(* Logix 5000 project; controller Test vendor 1 type 14 code 92 rev 33.11; software revision 33.03; part 2 of 3 *)
(* tags used below, declared in another part *)
   K50 : Banner_K50Display_v4;
   Port_Data : Banner_IOL_Port_v4;
   Port : DINT;
   Local_Control : DINT;
   Command_Being_Processed : BOOL;
   Update_Archive : BOOL;
   Index_Write_Control : DINT;
   Index_Write_Inprocess : INT;
   Inprocess_Index : DINT;
   SP_Index : DINT;   // State Parameters Index
   SP_Write_Index : DINT;
   SP_W_Index : DINT;
(* Banner_K50Display_Param_v4, continued *)

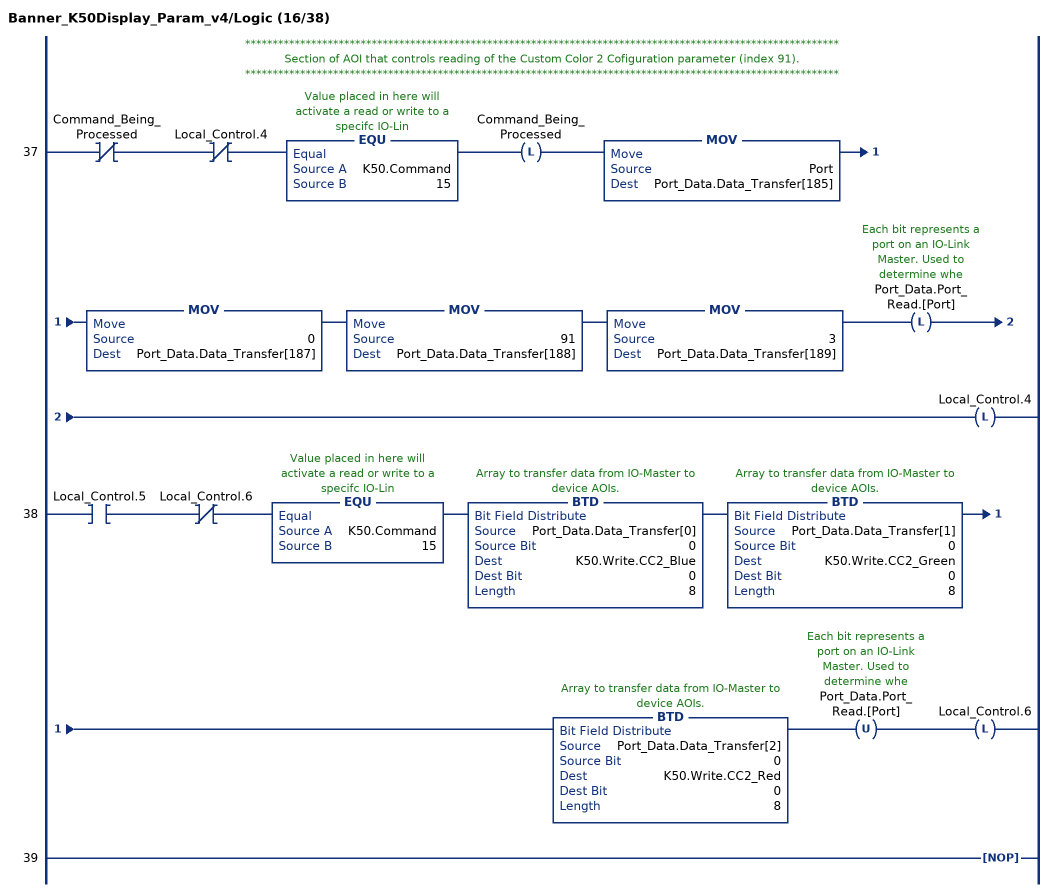
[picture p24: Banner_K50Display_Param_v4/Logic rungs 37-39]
   // ************************************************************************************************************
   // Section of AOI that controls reading of the Custom Color 2 Cofiguration parameter (index 91).
   // ************************************************************************************************************
   37: XIO(Command_Being_Processed)XIO(Local_Control.4)EQU(K50.Command,15)OTL(Command_Being_Processed)MOV(Port,Port_Data.Data_Transfer[185])MOV(0,Port_Data.Data_Transfer[187])MOV(91,Port_Data.Data_Transfer[188])MOV(3,Port_Data.Data_Transfer[189])OTL(Port_Data.Port_Read.[Port])OTL(Local_Control.4);
   38: XIC(Local_Control.5)XIO(Local_Control.6)EQU(K50.Command,15)BTD(Port_Data.Data_Transfer[0],0,K50.Write.CC2_Blue,0,8)BTD(Port_Data.Data_Transfer[1],0,K50.Write.CC2_Green,0,8)BTD(Port_Data.Data_Transfer[2],0,K50.Write.CC2_Red,0,8)OTU(Port_Data.Port_Read.[Port])OTL(Local_Control.6);
   39: NOP();
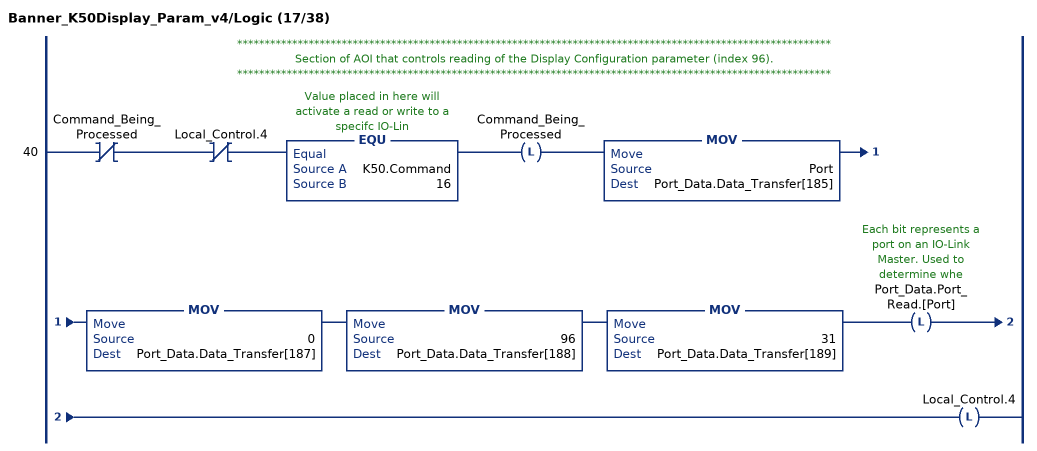
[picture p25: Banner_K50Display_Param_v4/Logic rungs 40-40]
   // ************************************************************************************************************
   // Section of AOI that controls reading of the Display Configuration parameter (index 96).
   // ************************************************************************************************************
   40: XIO(Command_Being_Processed)XIO(Local_Control.4)EQU(K50.Command,16)OTL(Command_Being_Processed)MOV(Port,Port_Data.Data_Transfer[185])MOV(0,Port_Data.Data_Transfer[187])MOV(96,Port_Data.Data_Transfer[188])MOV(31,Port_Data.Data_Transfer[189])OTL(Port_Data.Port_Read.[Port])OTL(Local_Control.4);
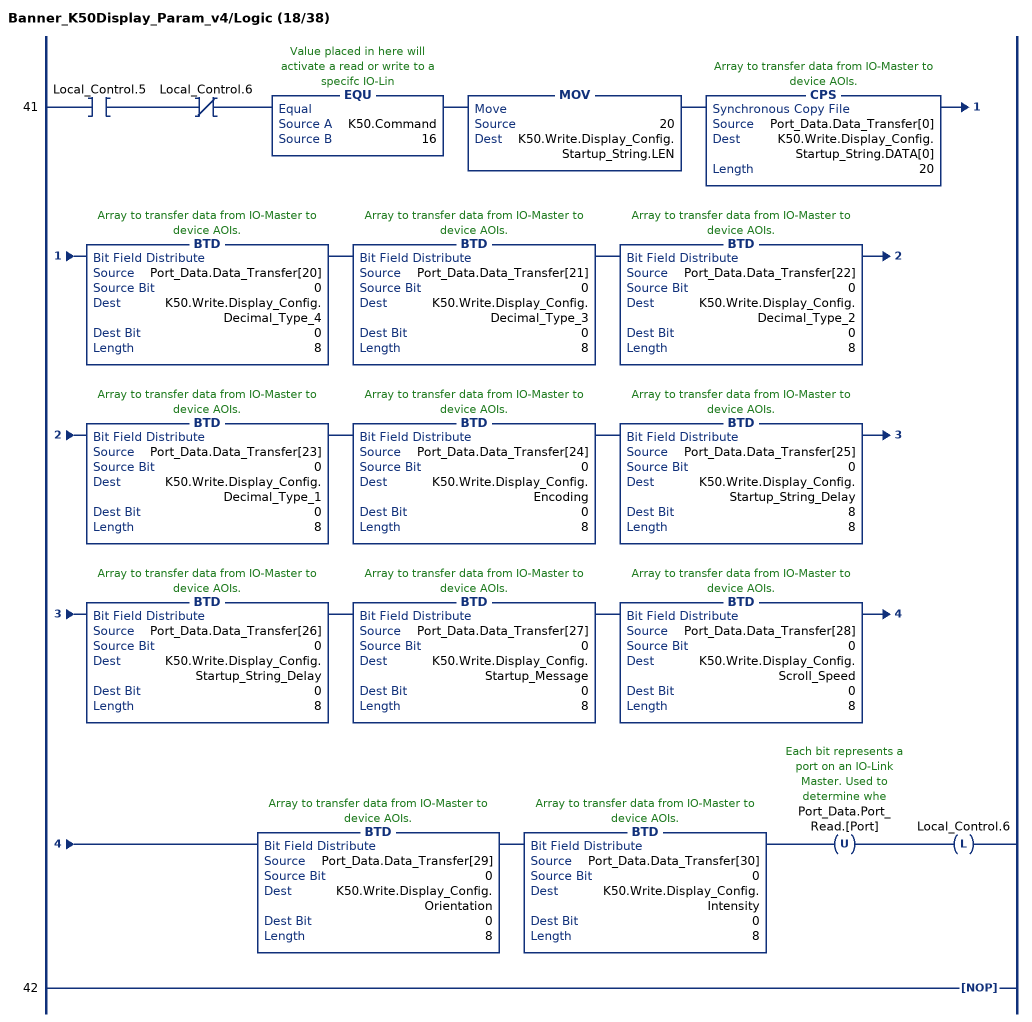
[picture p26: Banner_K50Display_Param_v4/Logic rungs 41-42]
   41: XIC(Local_Control.5)XIO(Local_Control.6)EQU(K50.Command,16)MOV(20,K50.Write.Display_Config.Startup_String.LEN)CPS(Port_Data.Data_Transfer[0],K50.Write.Display_Config.Startup_String.DATA[0],20)BTD(Port_Data.Data_Transfer[20],0,K50.Write.Display_Config.Decimal_Type_4,0,8)BTD(Port_Data.Data_Transfer[21],0,K50.Write.Display_Config.Decimal_Type_3,0,8)BTD(Port_Data.Data_Transfer[22],0,K50.Write.Display_Config.Decimal_Type_2,0,8)BTD(Port_Data.Data_Transfer[23],0,K50.Write.Display_Config.Decimal_Type_1,0,8)BTD(Port_Data.Data_Transfer[24],0,K50.Write.Display_Config.Encoding,0,8)BTD(Port_Data.Data_Transfer[25],0,K50.Write.Display_Config.Startup_String_Delay,8,8)BTD(Port_Data.Data_Transfer[26],0,K50.Write.Display_Config.Startup_String_Delay,0,8)BTD(Port_Data.Data_Transfer[27],0,K50.Write.Display_Config.Startup_Message,0,8)BTD(Port_Data.Data_Transfer[28],0,K50.Write.Display_Config.Scroll_Speed,0,8)BTD(Port_Data.Data_Transfer[29],0,K50.Write.Display_Config.Orientation,0,8)BTD(Port_Data.Data_Transfer[30],0,K50.Write.Display_Config.Intensity,0,8)OTU(Port_Data.Port_Read.[Port])OTL(Local_Control.6);
   42: NOP();
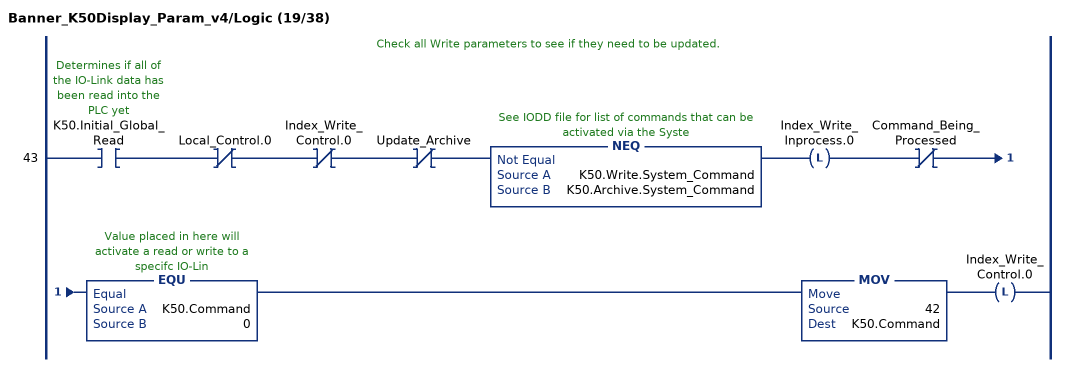
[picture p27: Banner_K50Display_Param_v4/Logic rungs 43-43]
   // Check all Write parameters to see if they need to be updated.
   43: XIC(K50.Initial_Global_Read)XIO(Local_Control.0)XIO(Index_Write_Control.0)XIO(Update_Archive)NEQ(K50.Write.System_Command,K50.Archive.System_Command)OTL(Index_Write_Inprocess.0)XIO(Command_Being_Processed)EQU(K50.Command,0)MOV(42,K50.Command)OTL(Index_Write_Control.0);
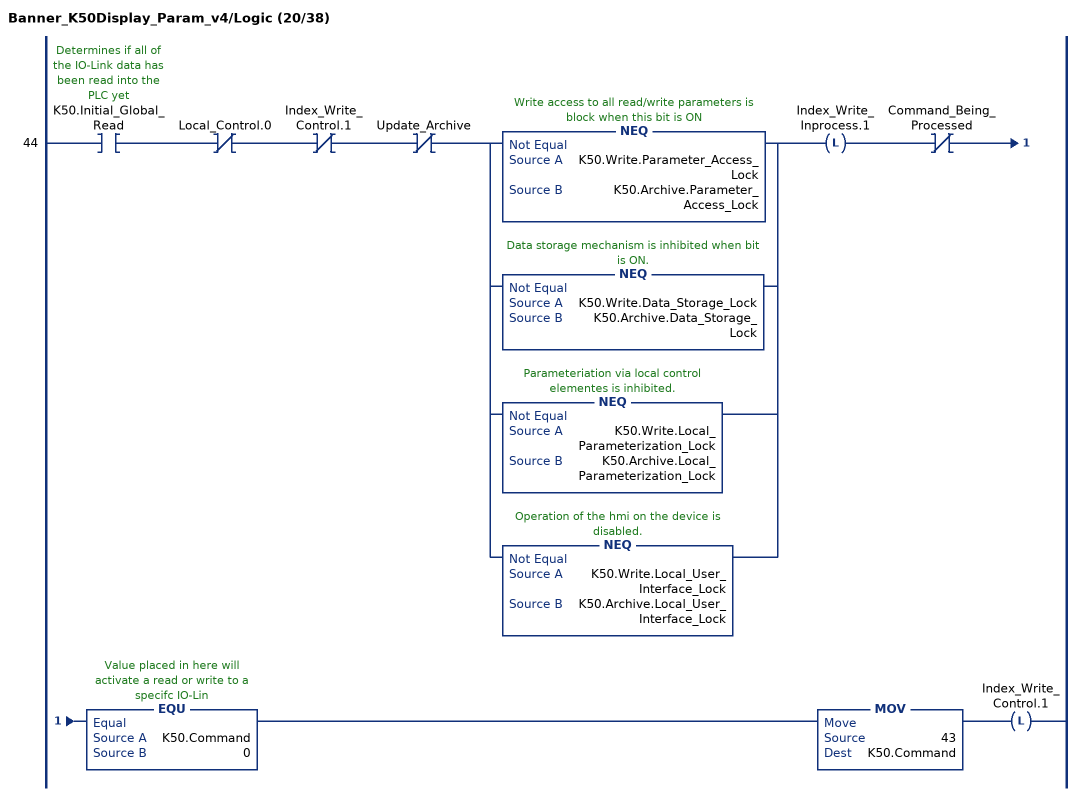
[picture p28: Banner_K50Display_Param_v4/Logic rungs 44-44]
   44: XIC(K50.Initial_Global_Read)XIO(Local_Control.0)XIO(Index_Write_Control.1)XIO(Update_Archive)[NEQ(K50.Write.Parameter_Access_Lock,K50.Archive.Parameter_Access_Lock) ,NEQ(K50.Write.Data_Storage_Lock,K50.Archive.Data_Storage_Lock) ,NEQ(K50.Write.Local_Parameterization_Lock,K50.Archive.Local_Parameterization_Lock) ,NEQ(K50.Write.Local_User_Interface_Lock,K50.Archive.Local_User_Interface_Lock) ]OTL(Index_Write_Inprocess.1)XIO(Command_Being_Processed)EQU(K50.Command,0)MOV(43,K50.Command)OTL(Index_Write_Control.1);
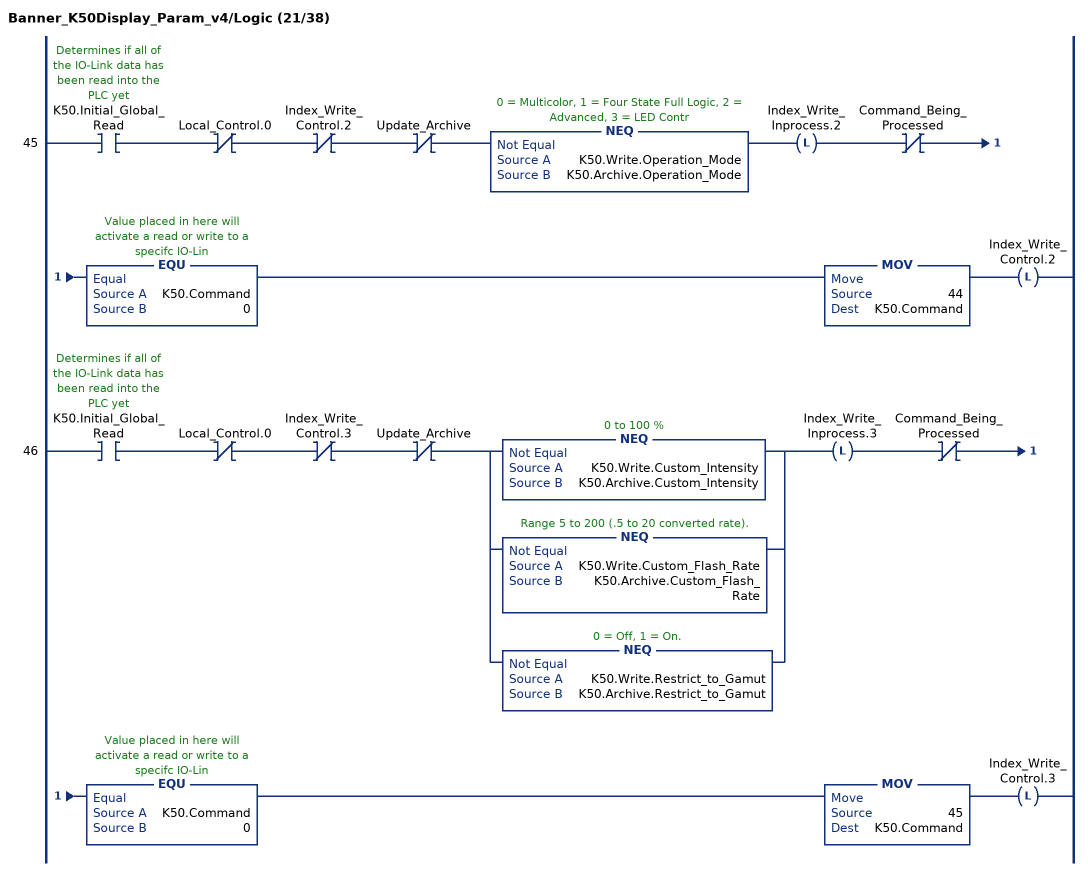
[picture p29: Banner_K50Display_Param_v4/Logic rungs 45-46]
   45: XIC(K50.Initial_Global_Read)XIO(Local_Control.0)XIO(Index_Write_Control.2)XIO(Update_Archive)NEQ(K50.Write.Operation_Mode,K50.Archive.Operation_Mode)OTL(Index_Write_Inprocess.2)XIO(Command_Being_Processed)EQU(K50.Command,0)MOV(44,K50.Command)OTL(Index_Write_Control.2);
   46: XIC(K50.Initial_Global_Read)XIO(Local_Control.0)XIO(Index_Write_Control.3)XIO(Update_Archive)[NEQ(K50.Write.Custom_Intensity,K50.Archive.Custom_Intensity) ,NEQ(K50.Write.Custom_Flash_Rate,K50.Archive.Custom_Flash_Rate) ,NEQ(K50.Write.Restrict_to_Gamut,K50.Archive.Restrict_to_Gamut) ]OTL(Index_Write_Inprocess.3)XIO(Command_Being_Processed)EQU(K50.Command,0)MOV(45,K50.Command)OTL(Index_Write_Control.3);
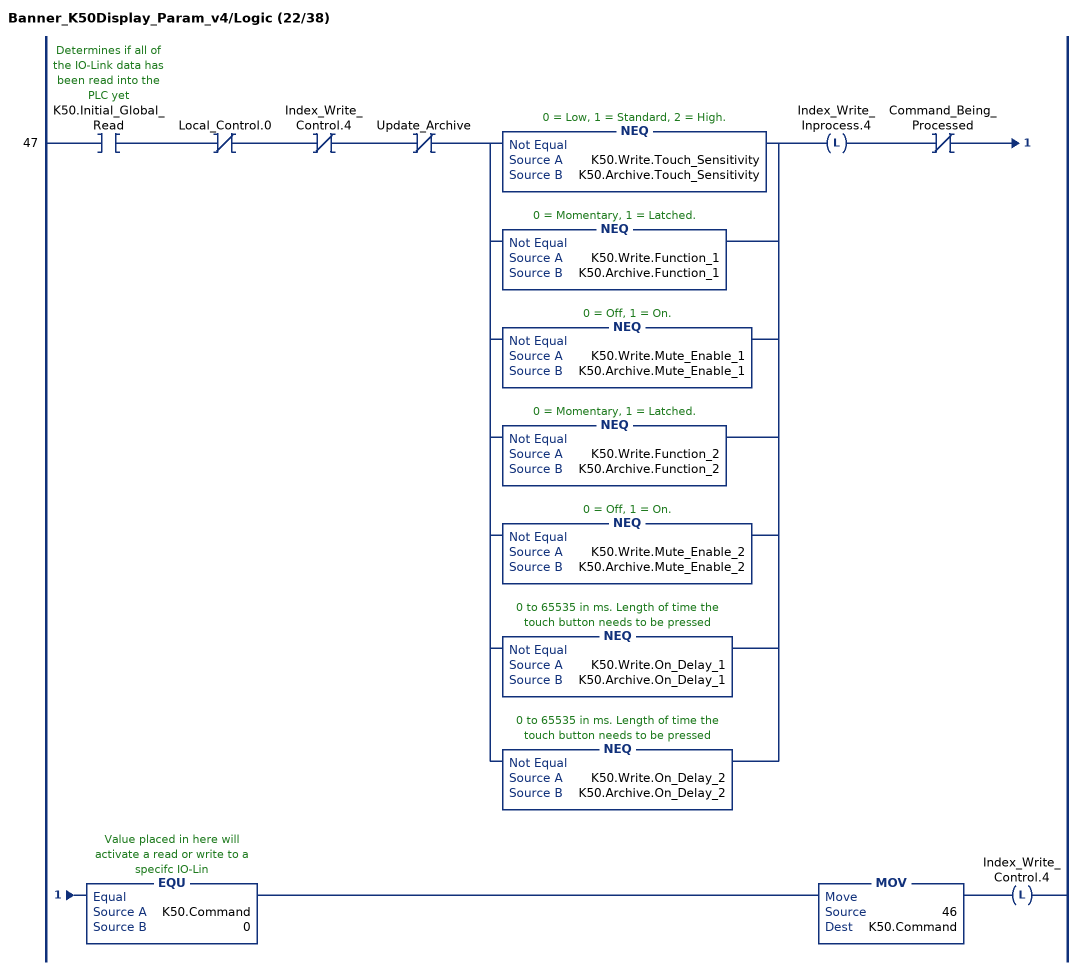
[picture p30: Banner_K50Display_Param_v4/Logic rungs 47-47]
   47: XIC(K50.Initial_Global_Read)XIO(Local_Control.0)XIO(Index_Write_Control.4)XIO(Update_Archive)[NEQ(K50.Write.Touch_Sensitivity,K50.Archive.Touch_Sensitivity) ,NEQ(K50.Write.Function_1,K50.Archive.Function_1) ,NEQ(K50.Write.Mute_Enable_1,K50.Archive.Mute_Enable_1) ,NEQ(K50.Write.Function_2,K50.Archive.Function_2) ,NEQ(K50.Write.Mute_Enable_2,K50.Archive.Mute_Enable_2) ,NEQ(K50.Write.On_Delay_1,K50.Archive.On_Delay_1) ,NEQ(K50.Write.On_Delay_2,K50.Archive.On_Delay_2) ]OTL(Index_Write_Inprocess.4)XIO(Command_Being_Processed)EQU(K50.Command,0)MOV(46,K50.Command)OTL(Index_Write_Control.4);
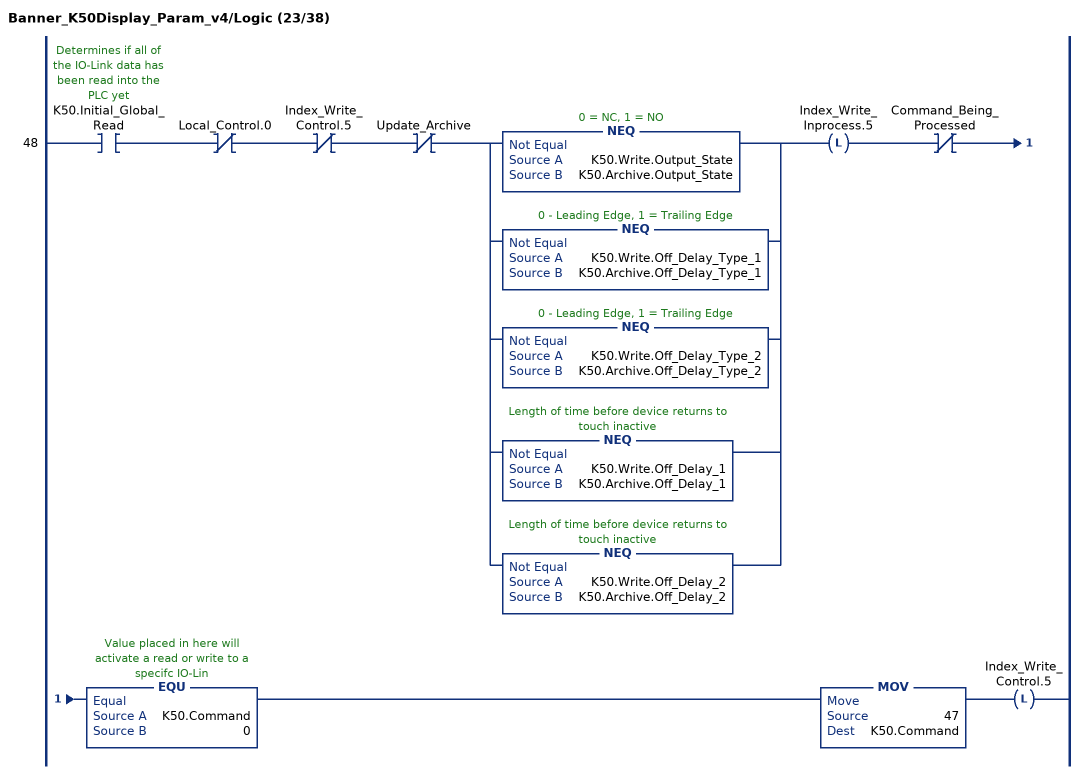
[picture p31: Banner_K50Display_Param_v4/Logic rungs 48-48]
   48: XIC(K50.Initial_Global_Read)XIO(Local_Control.0)XIO(Index_Write_Control.5)XIO(Update_Archive)[NEQ(K50.Write.Output_State,K50.Archive.Output_State) ,NEQ(K50.Write.Off_Delay_Type_1,K50.Archive.Off_Delay_Type_1) ,NEQ(K50.Write.Off_Delay_Type_2,K50.Archive.Off_Delay_Type_2) ,NEQ(K50.Write.Off_Delay_1,K50.Archive.Off_Delay_1) ,NEQ(K50.Write.Off_Delay_2,K50.Archive.Off_Delay_2) ]OTL(Index_Write_Inprocess.5)XIO(Command_Being_Processed)EQU(K50.Command,0)MOV(47,K50.Command)OTL(Index_Write_Control.5);
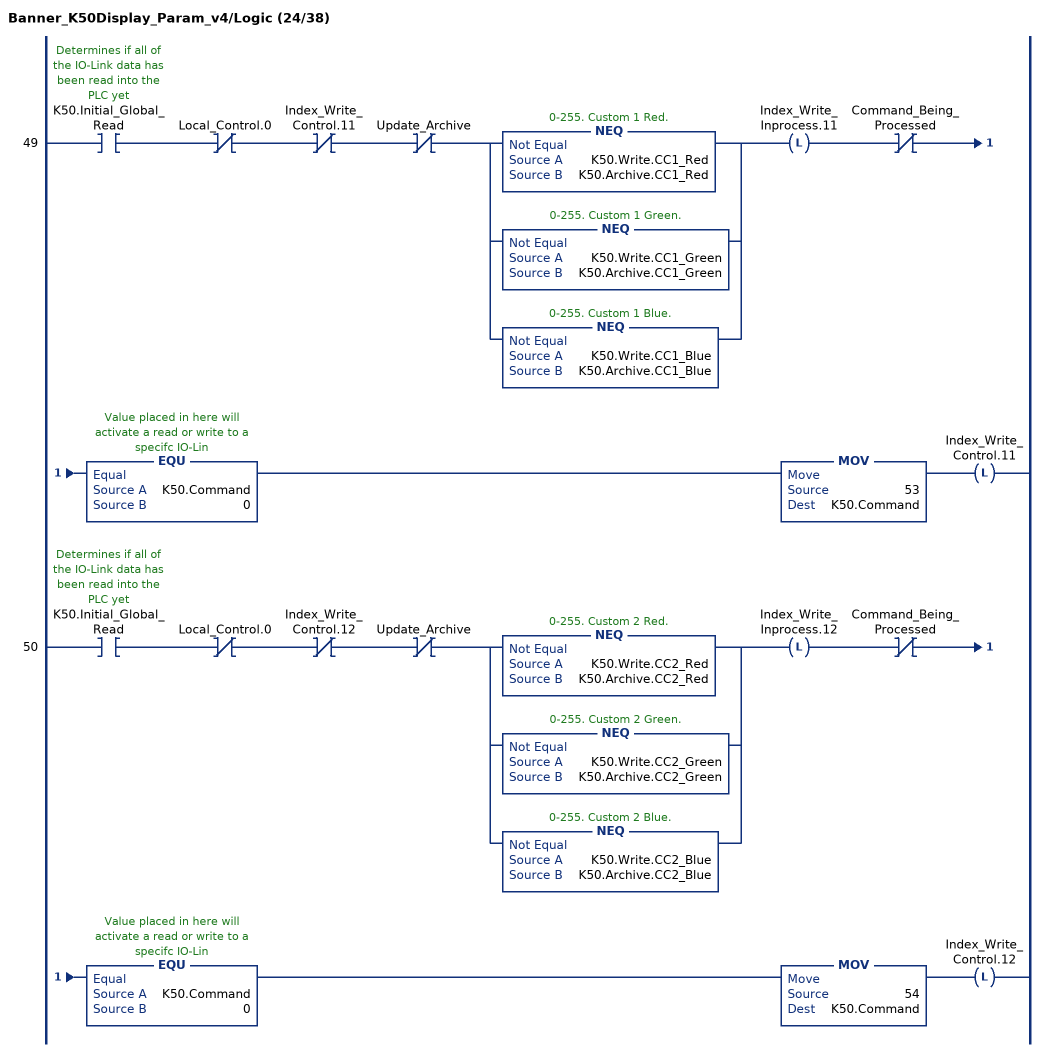
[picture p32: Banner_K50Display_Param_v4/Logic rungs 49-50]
   49: XIC(K50.Initial_Global_Read)XIO(Local_Control.0)XIO(Index_Write_Control.11)XIO(Update_Archive)[NEQ(K50.Write.CC1_Red,K50.Archive.CC1_Red) ,NEQ(K50.Write.CC1_Green,K50.Archive.CC1_Green) ,NEQ(K50.Write.CC1_Blue,K50.Archive.CC1_Blue) ]OTL(Index_Write_Inprocess.11)XIO(Command_Being_Processed)EQU(K50.Command,0)MOV(53,K50.Command)OTL(Index_Write_Control.11);
   50: XIC(K50.Initial_Global_Read)XIO(Local_Control.0)XIO(Index_Write_Control.12)XIO(Update_Archive)[NEQ(K50.Write.CC2_Red,K50.Archive.CC2_Red) ,NEQ(K50.Write.CC2_Green,K50.Archive.CC2_Green) ,NEQ(K50.Write.CC2_Blue,K50.Archive.CC2_Blue) ]OTL(Index_Write_Inprocess.12)XIO(Command_Being_Processed)EQU(K50.Command,0)MOV(54,K50.Command)OTL(Index_Write_Control.12);
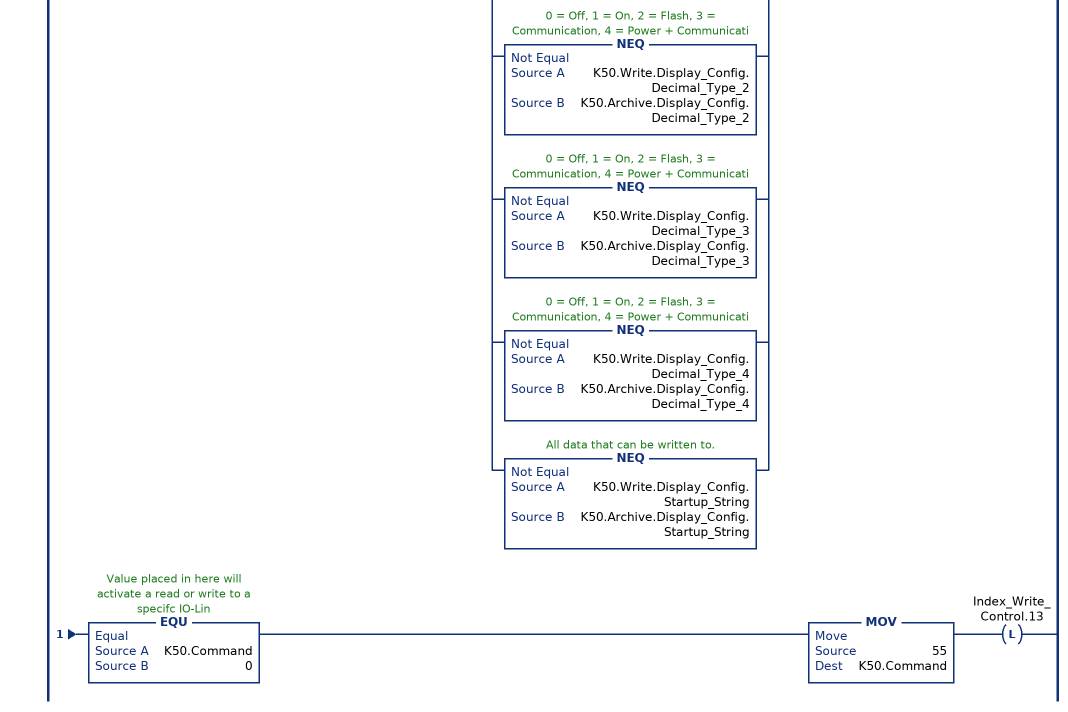
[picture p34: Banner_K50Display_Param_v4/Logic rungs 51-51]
   51: XIC(K50.Initial_Global_Read)XIO(Local_Control.0)XIO(Index_Write_Control.13)XIO(Update_Archive)[NEQ(K50.Write.Display_Config.Intensity,K50.Archive.Display_Config.Intensity) ,NEQ(K50.Write.Display_Config.Orientation,K50.Archive.Display_Config.Orientation) ,NEQ(K50.Write.Display_Config.Scroll_Speed,K50.Archive.Display_Config.Scroll_Speed) ,NEQ(K50.Write.Display_Config.Startup_Message,K50.Archive.Display_Config.Startup_Message) ,NEQ(K50.Write.Display_Config.Startup_String_Delay,K50.Archive.Display_Config.Startup_String_Delay) ,NEQ(K50.Write.Display_Config.Encoding,K50.Archive.Display_Config.Encoding) ,NEQ(K50.Write.Display_Config.Decimal_Type_1,K50.Archive.Display_Config.Decimal_Type_1) ,NEQ(K50.Write.Display_Config.Decimal_Type_2,K50.Archive.Display_Config.Decimal_Type_2) ,NEQ(K50.Write.Display_Config.Decimal_Type_3,K50.Archive.Display_Config.Decimal_Type_3) ,NEQ(K50.Write.Display_Config.Decimal_Type_4,K50.Archive.Display_Config.Decimal_Type_4) ,NEQ(K50.Write.Display_Config.Startup_String,K50.Archive.Display_Config.Startup_String) ]OTL(Index_Write_Inprocess.13)XIO(Command_Being_Processed)EQU(K50.Command,0)MOV(55,K50.Command)OTL(Index_Write_Control.13);
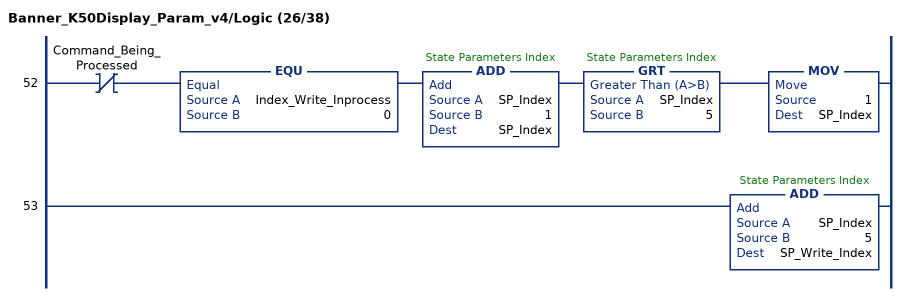
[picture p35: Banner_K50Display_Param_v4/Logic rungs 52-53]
   52: XIO(Command_Being_Processed)EQU(Index_Write_Inprocess,0)ADD(SP_Index,1,SP_Index)GRT(SP_Index,5)MOV(1,SP_Index);
   53: ADD(SP_Index,5,SP_Write_Index);
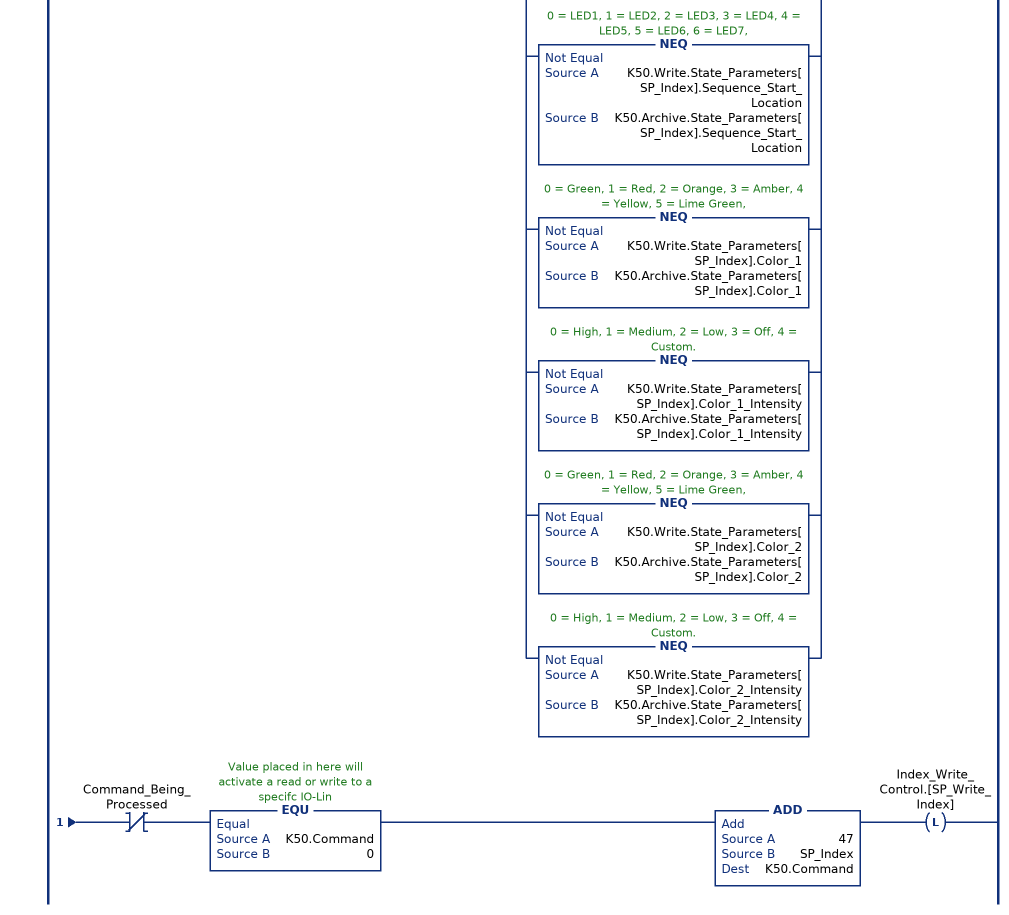
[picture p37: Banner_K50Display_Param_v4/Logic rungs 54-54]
   54: XIC(K50.Initial_Global_Read)XIO(Local_Control.0)XIO(Index_Write_Control.[SP_Write_Index])XIO(Update_Archive)[NEQ(K50.Write.State_Parameters[SP_Index].Type,K50.Archive.State_Parameters[SP_Index].Type) ,NEQ(K50.Write.State_Parameters[SP_Index].Direction,K50.Archive.State_Parameters[SP_Index].Direction) ,NEQ(K50.Write.State_Parameters[SP_Index].Pattern,K50.Archive.State_Parameters[SP_Index].Pattern) ,NEQ(K50.Write.State_Parameters[SP_Index].Speed,K50.Archive.State_Parameters[SP_Index].Speed) ,NEQ(K50.Write.State_Parameters[SP_Index].Off_Delay_Type,K50.Archive.State_Parameters[SP_Index].Off_Delay_Type) ,NEQ(K50.Write.State_Parameters[SP_Index].Off_Delay,K50.Archive.State_Parameters[SP_Index].Off_Delay) ,NEQ(K50.Write.State_Parameters[SP_Index].Static_Sequence,K50.Archive.State_Parameters[SP_Index].Static_Sequence) ,NEQ(K50.Write.State_Parameters[SP_Index].Sequence_Start_Location,K50.Archive.State_Parameters[SP_Index].Sequence_Start_Location) ,NEQ(K50.Write.State_Parameters[SP_Index].Color_1,K50.Archive.State_Parameters[SP_Index].Color_1) ,NEQ(K50.Write.State_Parameters[SP_Index].Color_1_Intensity,K50.Archive.State_Parameters[SP_Index].Color_1_Intensity) ,NEQ(K50.Write.State_Parameters[SP_Index].Color_2,K50.Archive.State_Parameters[SP_Index].Color_2) ,NEQ(K50.Write.State_Parameters[SP_Index].Color_2_Intensity,K50.Archive.State_Parameters[SP_Index].Color_2_Intensity) ]OTL(Index_Write_Inprocess.[SP_Write_Index])XIO(Command_Being_Processed)EQU(K50.Command,0)ADD(47,SP_Index,K50.Command)OTL(Index_Write_Control.[SP_Write_Index]);
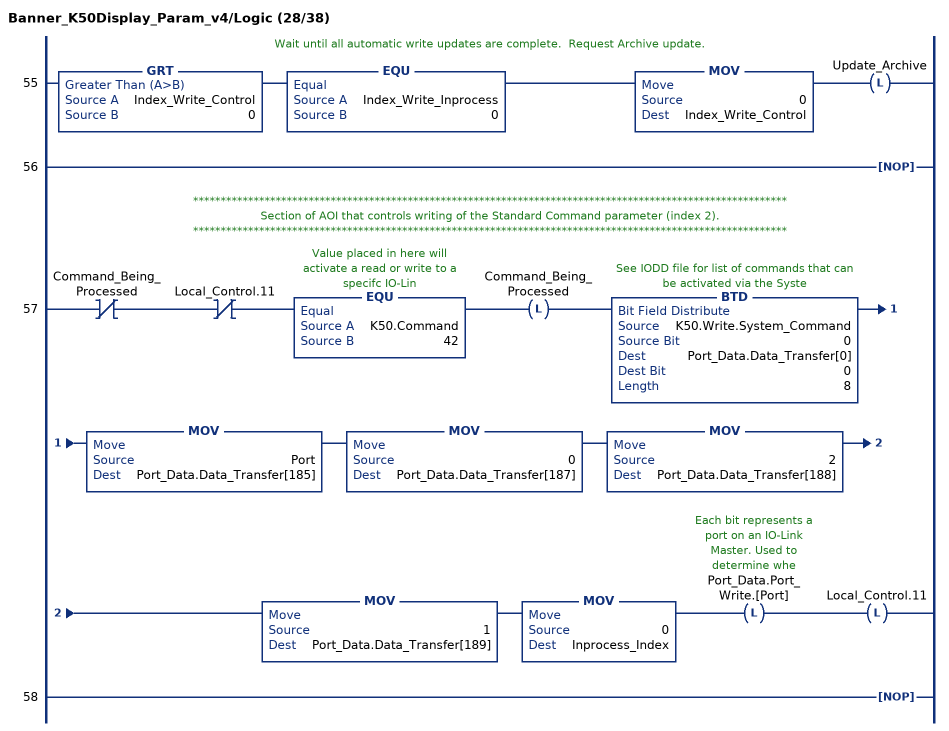
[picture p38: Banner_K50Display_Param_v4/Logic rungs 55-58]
   // Wait until all automatic write updates are complete.  Request Archive update.
   55: GRT(Index_Write_Control,0)EQU(Index_Write_Inprocess,0)MOV(0,Index_Write_Control)OTL(Update_Archive);
   56: NOP();
   // ************************************************************************************************************
   // Section of AOI that controls writing of the Standard Command parameter (index 2).
   // ************************************************************************************************************
   57: XIO(Command_Being_Processed)XIO(Local_Control.11)EQU(K50.Command,42)OTL(Command_Being_Processed)BTD(K50.Write.System_Command,0,Port_Data.Data_Transfer[0],0,8)MOV(Port,Port_Data.Data_Transfer[185])MOV(0,Port_Data.Data_Transfer[187])MOV(2,Port_Data.Data_Transfer[188])MOV(1,Port_Data.Data_Transfer[189])MOV(0,Inprocess_Index)OTL(Port_Data.Port_Write.[Port])OTL(Local_Control.11);
   58: NOP();
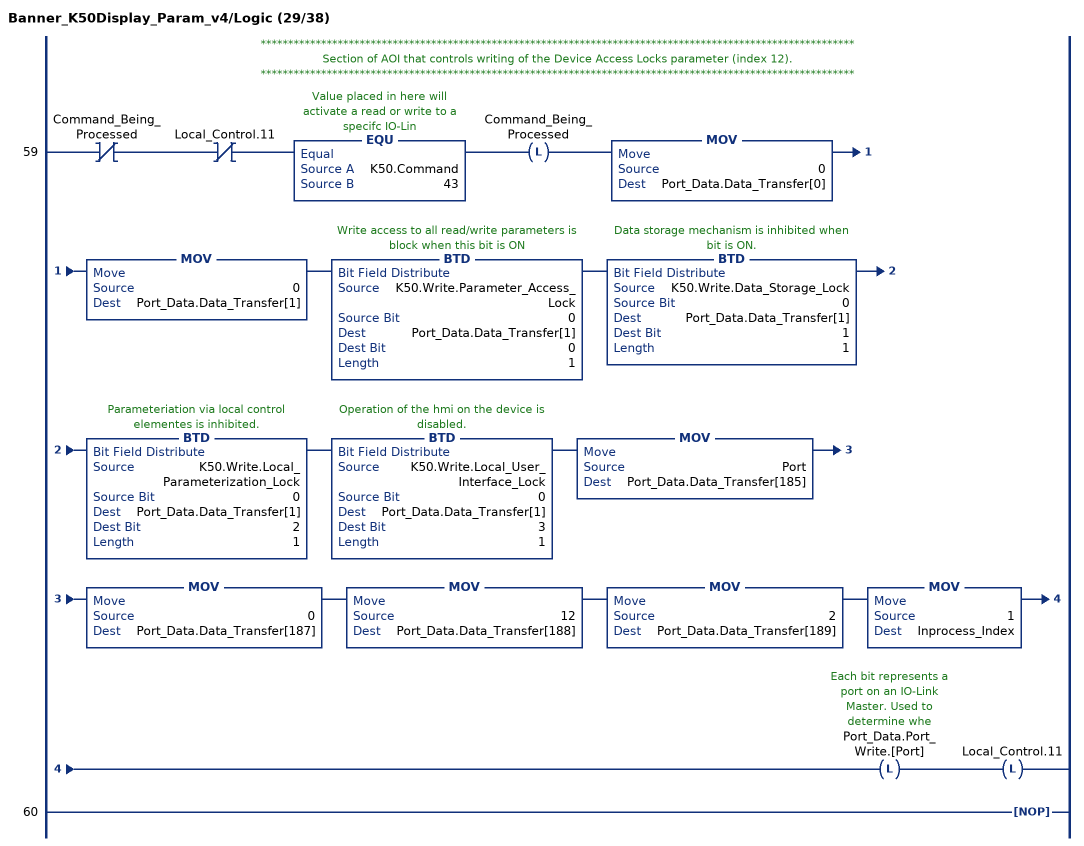
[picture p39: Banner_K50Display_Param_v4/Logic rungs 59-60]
   // ************************************************************************************************************
   // Section of AOI that controls writing of the Device Access Locks parameter (index 12).
   // ************************************************************************************************************
   59: XIO(Command_Being_Processed)XIO(Local_Control.11)EQU(K50.Command,43)OTL(Command_Being_Processed)MOV(0,Port_Data.Data_Transfer[0])MOV(0,Port_Data.Data_Transfer[1])BTD(K50.Write.Parameter_Access_Lock,0,Port_Data.Data_Transfer[1],0,1)BTD(K50.Write.Data_Storage_Lock,0,Port_Data.Data_Transfer[1],1,1)BTD(K50.Write.Local_Parameterization_Lock,0,Port_Data.Data_Transfer[1],2,1)BTD(K50.Write.Local_User_Interface_Lock,0,Port_Data.Data_Transfer[1],3,1)MOV(Port,Port_Data.Data_Transfer[185])MOV(0,Port_Data.Data_Transfer[187])MOV(12,Port_Data.Data_Transfer[188])MOV(2,Port_Data.Data_Transfer[189])MOV(1,Inprocess_Index)OTL(Port_Data.Port_Write.[Port])OTL(Local_Control.11);
   60: NOP();
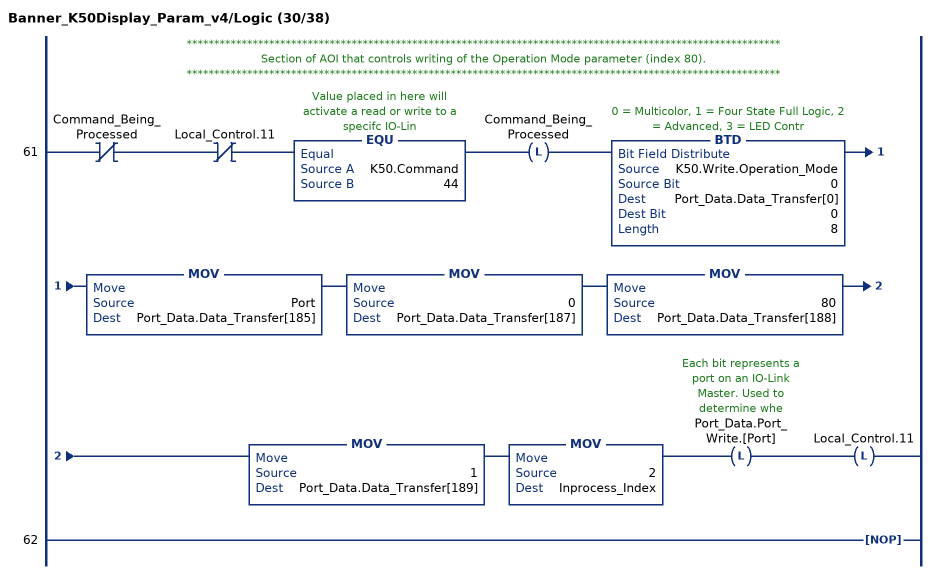
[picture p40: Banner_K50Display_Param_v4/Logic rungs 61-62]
   // ************************************************************************************************************
   // Section of AOI that controls writing of the Operation Mode parameter (index 80).
   // ************************************************************************************************************
   61: XIO(Command_Being_Processed)XIO(Local_Control.11)EQU(K50.Command,44)OTL(Command_Being_Processed)BTD(K50.Write.Operation_Mode,0,Port_Data.Data_Transfer[0],0,8)MOV(Port,Port_Data.Data_Transfer[185])MOV(0,Port_Data.Data_Transfer[187])MOV(80,Port_Data.Data_Transfer[188])MOV(1,Port_Data.Data_Transfer[189])MOV(2,Inprocess_Index)OTL(Port_Data.Port_Write.[Port])OTL(Local_Control.11);
   62: NOP();
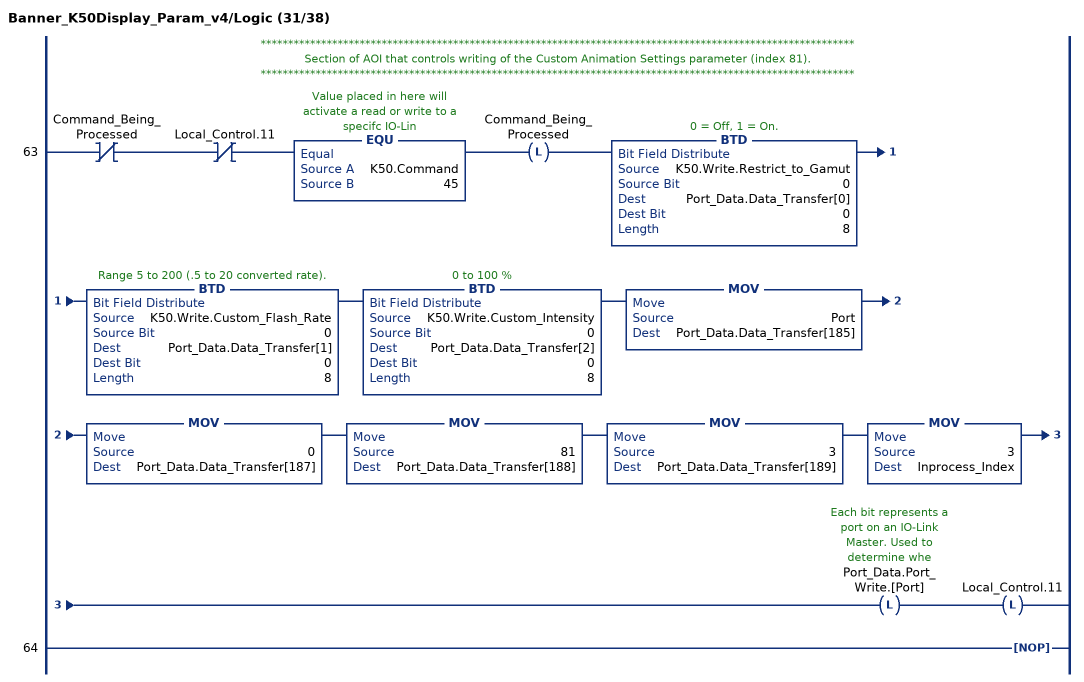
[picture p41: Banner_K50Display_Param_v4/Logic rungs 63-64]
   // ************************************************************************************************************
   // Section of AOI that controls writing of the Custom Animation Settings parameter (index 81).
   // ************************************************************************************************************
   63: XIO(Command_Being_Processed)XIO(Local_Control.11)EQU(K50.Command,45)OTL(Command_Being_Processed)BTD(K50.Write.Restrict_to_Gamut,0,Port_Data.Data_Transfer[0],0,8)BTD(K50.Write.Custom_Flash_Rate,0,Port_Data.Data_Transfer[1],0,8)BTD(K50.Write.Custom_Intensity,0,Port_Data.Data_Transfer[2],0,8)MOV(Port,Port_Data.Data_Transfer[185])MOV(0,Port_Data.Data_Transfer[187])MOV(81,Port_Data.Data_Transfer[188])MOV(3,Port_Data.Data_Transfer[189])MOV(3,Inprocess_Index)OTL(Port_Data.Port_Write.[Port])OTL(Local_Control.11);
   64: NOP();
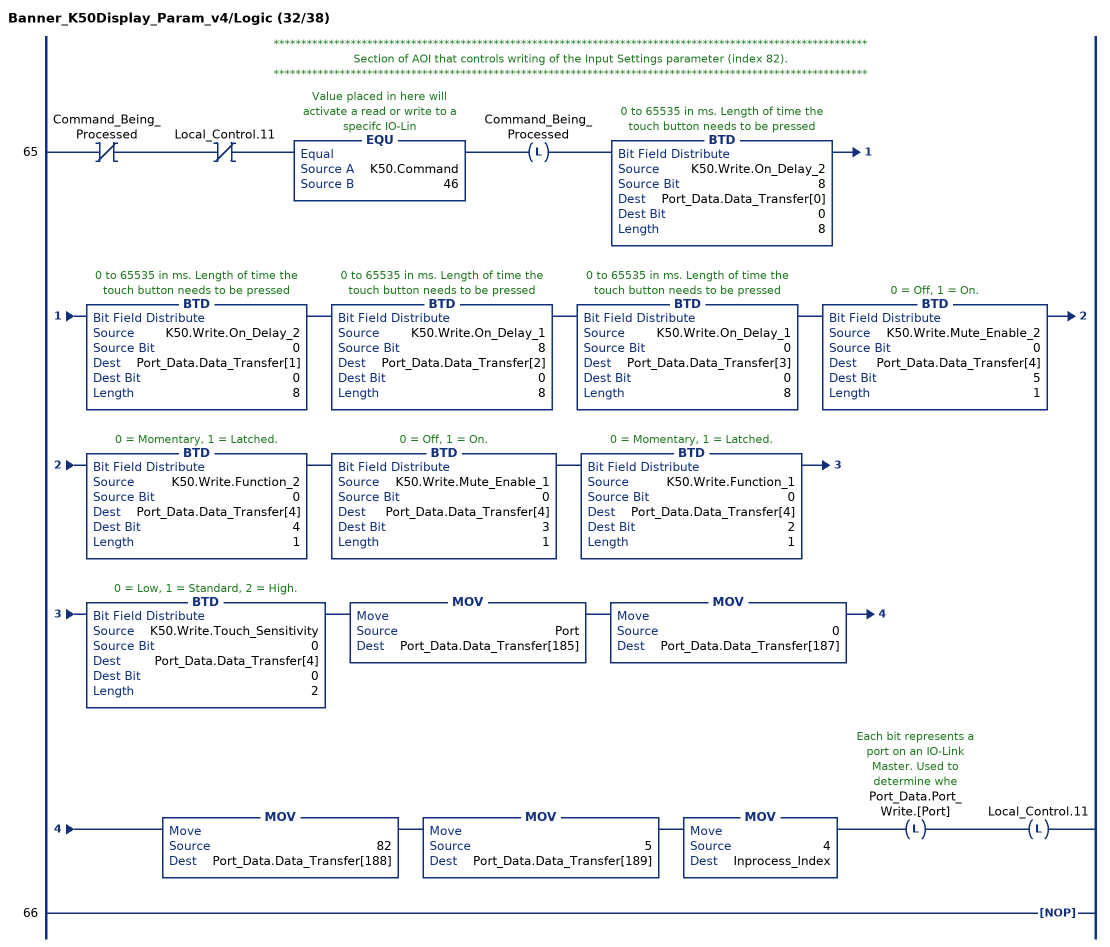
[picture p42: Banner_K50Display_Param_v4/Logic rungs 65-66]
   // ************************************************************************************************************
   // Section of AOI that controls writing of the Input Settings parameter (index 82).
   // ************************************************************************************************************
   65: XIO(Command_Being_Processed)XIO(Local_Control.11)EQU(K50.Command,46)OTL(Command_Being_Processed)BTD(K50.Write.On_Delay_2,8,Port_Data.Data_Transfer[0],0,8)BTD(K50.Write.On_Delay_2,0,Port_Data.Data_Transfer[1],0,8)BTD(K50.Write.On_Delay_1,8,Port_Data.Data_Transfer[2],0,8)BTD(K50.Write.On_Delay_1,0,Port_Data.Data_Transfer[3],0,8)BTD(K50.Write.Mute_Enable_2,0,Port_Data.Data_Transfer[4],5,1)BTD(K50.Write.Function_2,0,Port_Data.Data_Transfer[4],4,1)BTD(K50.Write.Mute_Enable_1,0,Port_Data.Data_Transfer[4],3,1)BTD(K50.Write.Function_1,0,Port_Data.Data_Transfer[4],2,1)BTD(K50.Write.Touch_Sensitivity,0,Port_Data.Data_Transfer[4],0,2)MOV(Port,Port_Data.Data_Transfer[185])MOV(0,Port_Data.Data_Transfer[187])MOV(82,Port_Data.Data_Transfer[188])MOV(5,Port_Data.Data_Transfer[189])MOV(4,Inprocess_Index)OTL(Port_Data.Port_Write.[Port])OTL(Local_Control.11);
   66: NOP();
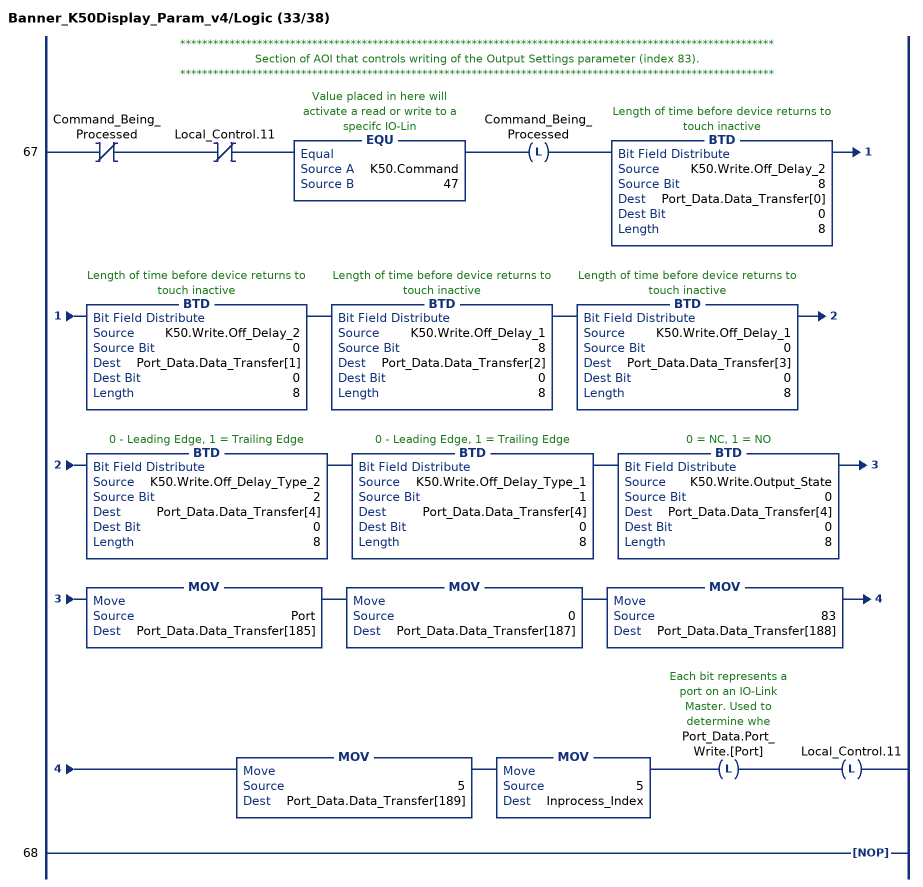
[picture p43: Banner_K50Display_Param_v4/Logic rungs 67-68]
   // ************************************************************************************************************
   // Section of AOI that controls writing of the Output Settings parameter (index 83).
   // ************************************************************************************************************
   67: XIO(Command_Being_Processed)XIO(Local_Control.11)EQU(K50.Command,47)OTL(Command_Being_Processed)BTD(K50.Write.Off_Delay_2,8,Port_Data.Data_Transfer[0],0,8)BTD(K50.Write.Off_Delay_2,0,Port_Data.Data_Transfer[1],0,8)BTD(K50.Write.Off_Delay_1,8,Port_Data.Data_Transfer[2],0,8)BTD(K50.Write.Off_Delay_1,0,Port_Data.Data_Transfer[3],0,8)BTD(K50.Write.Off_Delay_Type_2,2,Port_Data.Data_Transfer[4],0,8)BTD(K50.Write.Off_Delay_Type_1,1,Port_Data.Data_Transfer[4],0,8)BTD(K50.Write.Output_State,0,Port_Data.Data_Transfer[4],0,8)MOV(Port,Port_Data.Data_Transfer[185])MOV(0,Port_Data.Data_Transfer[187])MOV(83,Port_Data.Data_Transfer[188])MOV(5,Port_Data.Data_Transfer[189])MOV(5,Inprocess_Index)OTL(Port_Data.Port_Write.[Port])OTL(Local_Control.11);
   68: NOP();
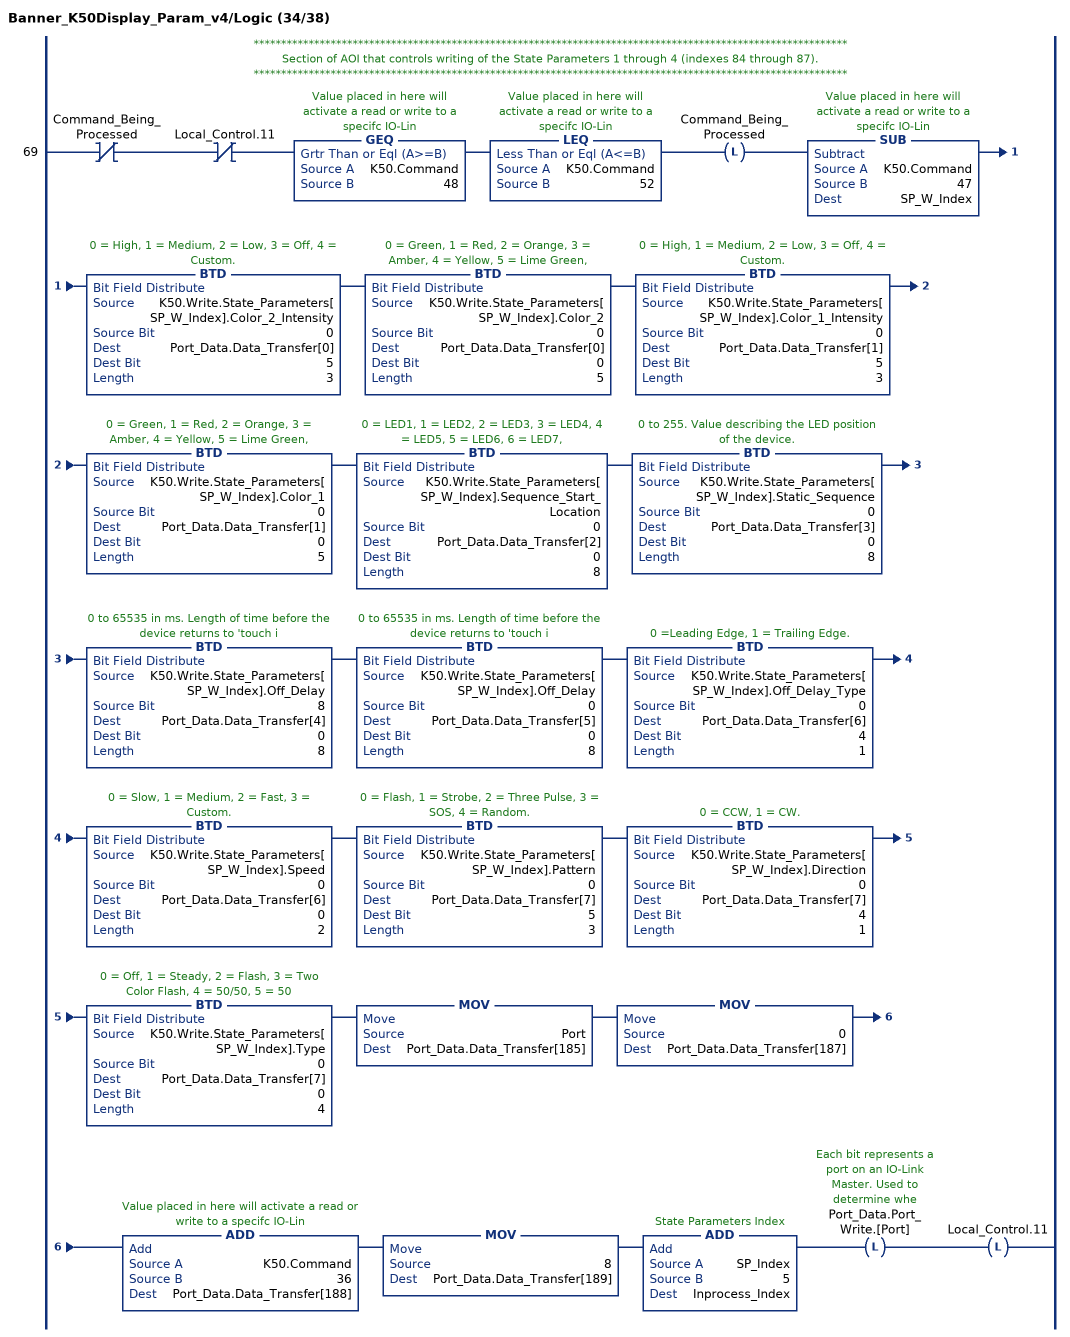
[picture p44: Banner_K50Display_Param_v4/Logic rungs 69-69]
   // ************************************************************************************************************
   // Section of AOI that controls writing of the State Parameters 1 through 4 (indexes 84 through 87).
   // ************************************************************************************************************
   69: XIO(Command_Being_Processed)XIO(Local_Control.11)GEQ(K50.Command,48)LEQ(K50.Command,52)OTL(Command_Being_Processed)SUB(K50.Command,47,SP_W_Index)BTD(K50.Write.State_Parameters[SP_W_Index].Color_2_Intensity,0,Port_Data.Data_Transfer[0],5,3)BTD(K50.Write.State_Parameters[SP_W_Index].Color_2,0,Port_Data.Data_Transfer[0],0,5)BTD(K50.Write.State_Parameters[SP_W_Index].Color_1_Intensity,0,Port_Data.Data_Transfer[1],5,3)BTD(K50.Write.State_Parameters[SP_W_Index].Color_1,0,Port_Data.Data_Transfer[1],0,5)BTD(K50.Write.State_Parameters[SP_W_Index].Sequence_Start_Location,0,Port_Data.Data_Transfer[2],0,8)BTD(K50.Write.State_Parameters[SP_W_Index].Static_Sequence,0,Port_Data.Data_Transfer[3],0,8)BTD(K50.Write.State_Parameters[SP_W_Index].Off_Delay,8,Port_Data.Data_Transfer[4],0,8)BTD(K50.Write.State_Parameters[SP_W_Index].Off_Delay,0,Port_Data.Data_Transfer[5],0,8)BTD(K50.Write.State_Parameters[SP_W_Index].Off_Delay_Type,0,Port_Data.Data_Transfer[6],4,1)BTD(K50.Write.State_Parameters[SP_W_Index].Speed,0,Port_Data.Data_Transfer[6],0,2)BTD(K50.Write.State_Parameters[SP_W_Index].Pattern,0,Port_Data.Data_Transfer[7],5,3)BTD(K50.Write.State_Parameters[SP_W_Index].Direction,0,Port_Data.Data_Transfer[7],4,1)BTD(K50.Write.State_Parameters[SP_W_Index].Type,0,Port_Data.Data_Transfer[7],0,4)MOV(Port,Port_Data.Data_Transfer[185])MOV(0,Port_Data.Data_Transfer[187])ADD(K50.Command,36,Port_Data.Data_Transfer[188])MOV(8,Port_Data.Data_Transfer[189])ADD(SP_Index,5,Inprocess_Index)OTL(Port_Data.Port_Write.[Port])OTL(Local_Control.11);
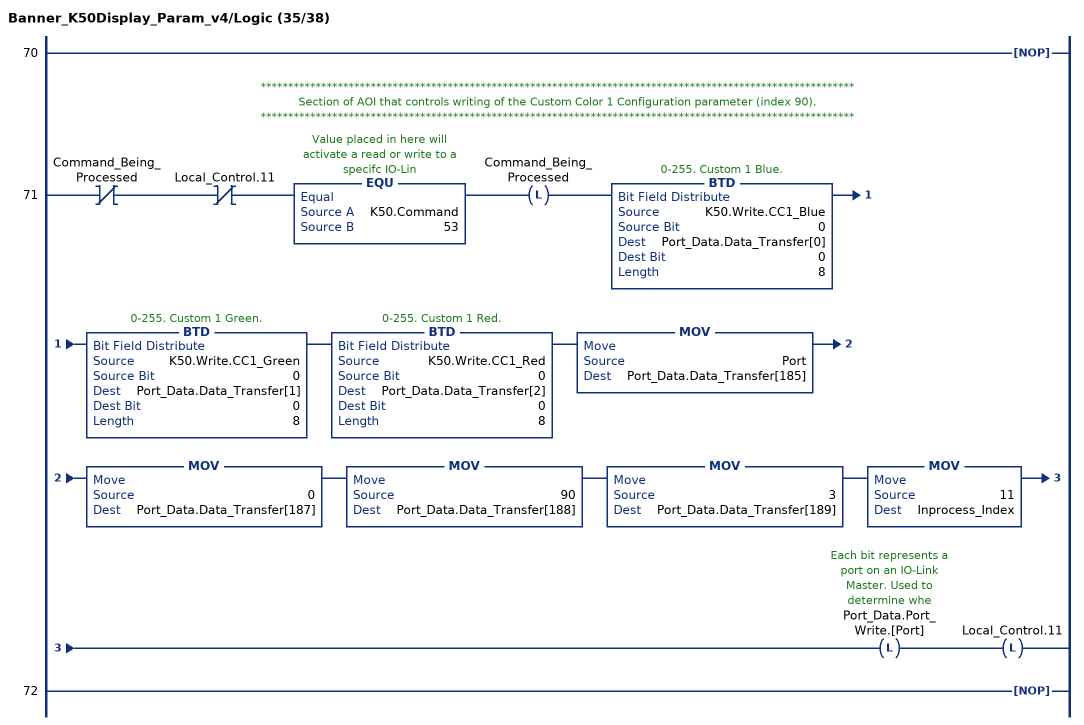
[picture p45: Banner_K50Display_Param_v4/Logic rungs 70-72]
   70: NOP();
   // ************************************************************************************************************
   // Section of AOI that controls writing of the Custom Color 1 Configuration parameter (index 90).
   // ************************************************************************************************************
   71: XIO(Command_Being_Processed)XIO(Local_Control.11)EQU(K50.Command,53)OTL(Command_Being_Processed)BTD(K50.Write.CC1_Blue,0,Port_Data.Data_Transfer[0],0,8)BTD(K50.Write.CC1_Green,0,Port_Data.Data_Transfer[1],0,8)BTD(K50.Write.CC1_Red,0,Port_Data.Data_Transfer[2],0,8)MOV(Port,Port_Data.Data_Transfer[185])MOV(0,Port_Data.Data_Transfer[187])MOV(90,Port_Data.Data_Transfer[188])MOV(3,Port_Data.Data_Transfer[189])MOV(11,Inprocess_Index)OTL(Port_Data.Port_Write.[Port])OTL(Local_Control.11);
   72: NOP();
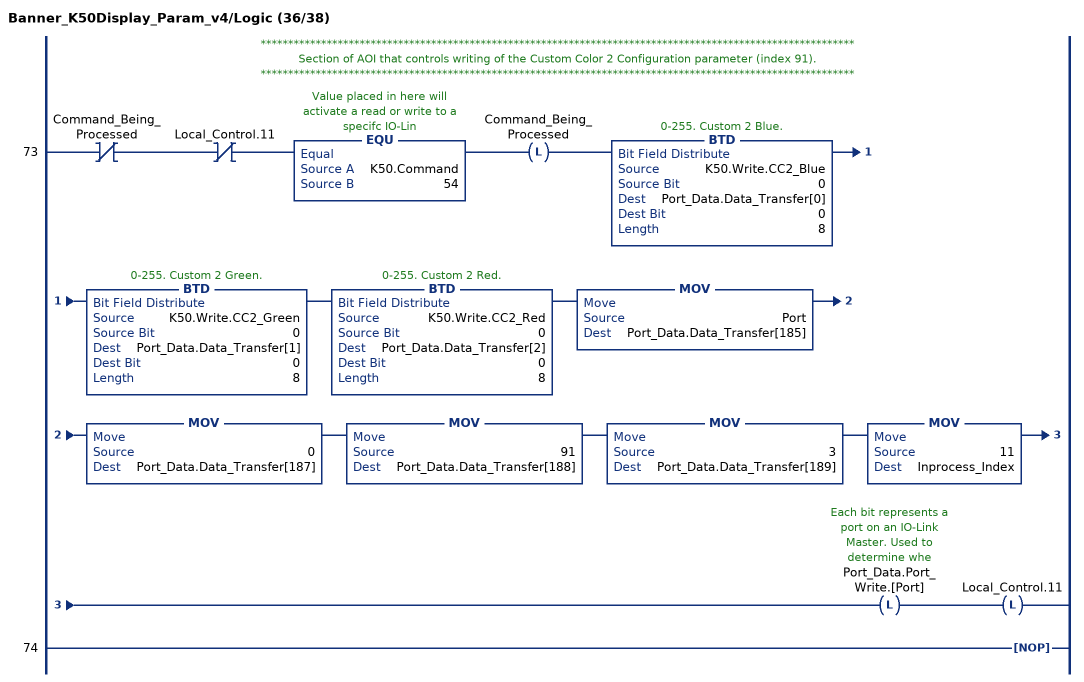
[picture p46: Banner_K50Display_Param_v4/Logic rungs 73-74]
   // ************************************************************************************************************
   // Section of AOI that controls writing of the Custom Color 2 Configuration parameter (index 91).
   // ************************************************************************************************************
   73: XIO(Command_Being_Processed)XIO(Local_Control.11)EQU(K50.Command,54)OTL(Command_Being_Processed)BTD(K50.Write.CC2_Blue,0,Port_Data.Data_Transfer[0],0,8)BTD(K50.Write.CC2_Green,0,Port_Data.Data_Transfer[1],0,8)BTD(K50.Write.CC2_Red,0,Port_Data.Data_Transfer[2],0,8)MOV(Port,Port_Data.Data_Transfer[185])MOV(0,Port_Data.Data_Transfer[187])MOV(91,Port_Data.Data_Transfer[188])MOV(3,Port_Data.Data_Transfer[189])MOV(11,Inprocess_Index)OTL(Port_Data.Port_Write.[Port])OTL(Local_Control.11);
   74: NOP();
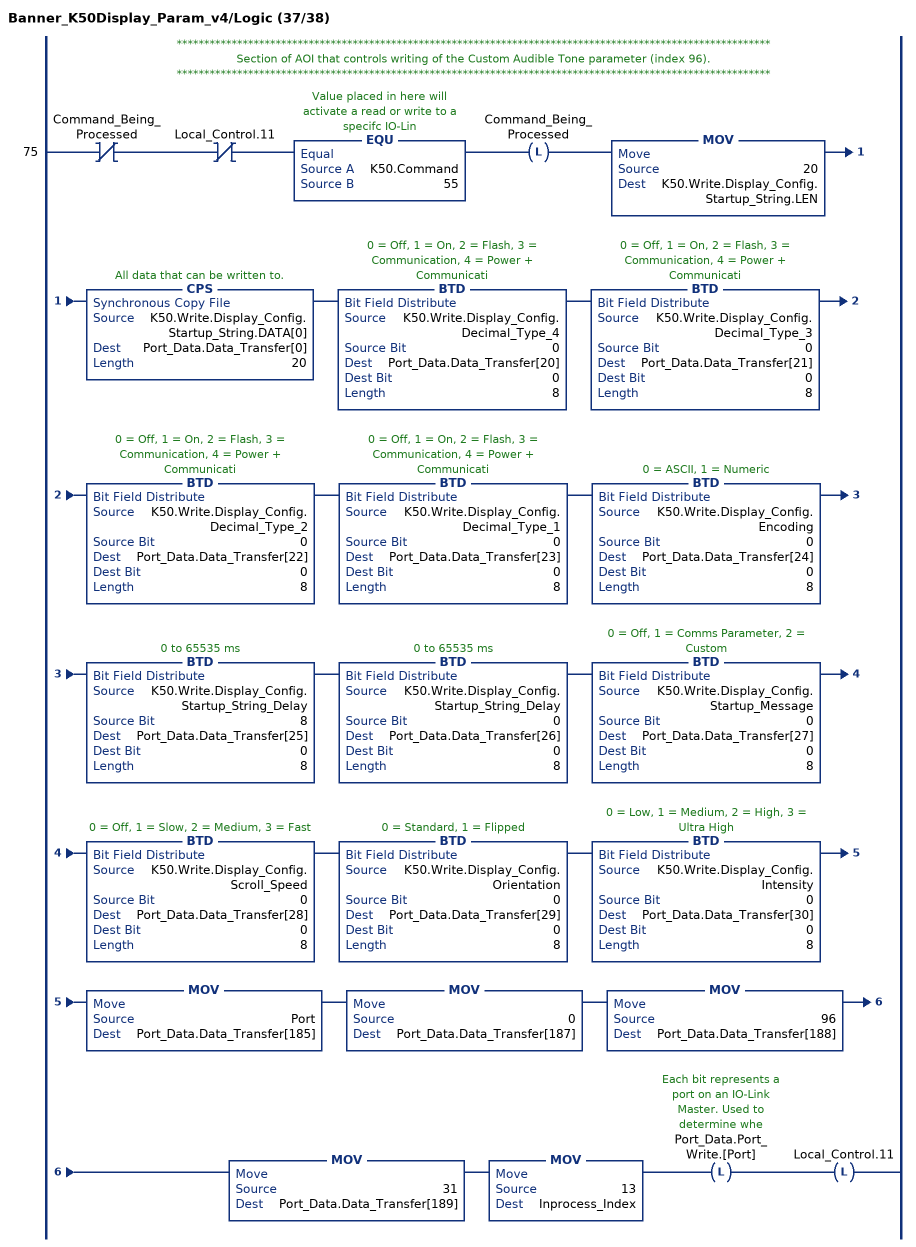
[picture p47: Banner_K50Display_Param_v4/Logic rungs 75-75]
   // ************************************************************************************************************
   // Section of AOI that controls writing of the Custom Audible Tone parameter (index 96).
   // ************************************************************************************************************
   75: XIO(Command_Being_Processed)XIO(Local_Control.11)EQU(K50.Command,55)OTL(Command_Being_Processed)MOV(20,K50.Write.Display_Config.Startup_String.LEN)CPS(K50.Write.Display_Config.Startup_String.DATA[0],Port_Data.Data_Transfer[0],20)BTD(K50.Write.Display_Config.Decimal_Type_4,0,Port_Data.Data_Transfer[20],0,8)BTD(K50.Write.Display_Config.Decimal_Type_3,0,Port_Data.Data_Transfer[21],0,8)BTD(K50.Write.Display_Config.Decimal_Type_2,0,Port_Data.Data_Transfer[22],0,8)BTD(K50.Write.Display_Config.Decimal_Type_1,0,Port_Data.Data_Transfer[23],0,8)BTD(K50.Write.Display_Config.Encoding,0,Port_Data.Data_Transfer[24],0,8)BTD(K50.Write.Display_Config.Startup_String_Delay,8,Port_Data.Data_Transfer[25],0,8)BTD(K50.Write.Display_Config.Startup_String_Delay,0,Port_Data.Data_Transfer[26],0,8)BTD(K50.Write.Display_Config.Startup_Message,0,Port_Data.Data_Transfer[27],0,8)BTD(K50.Write.Display_Config.Scroll_Speed,0,Port_Data.Data_Transfer[28],0,8)BTD(K50.Write.Display_Config.Orientation,0,Port_Data.Data_Transfer[29],0,8)BTD(K50.Write.Display_Config.Intensity,0,Port_Data.Data_Transfer[30],0,8)MOV(Port,Port_Data.Data_Transfer[185])MOV(0,Port_Data.Data_Transfer[187])MOV(96,Port_Data.Data_Transfer[188])MOV(31,Port_Data.Data_Transfer[189])MOV(13,Inprocess_Index)OTL(Port_Data.Port_Write.[Port])OTL(Local_Control.11);
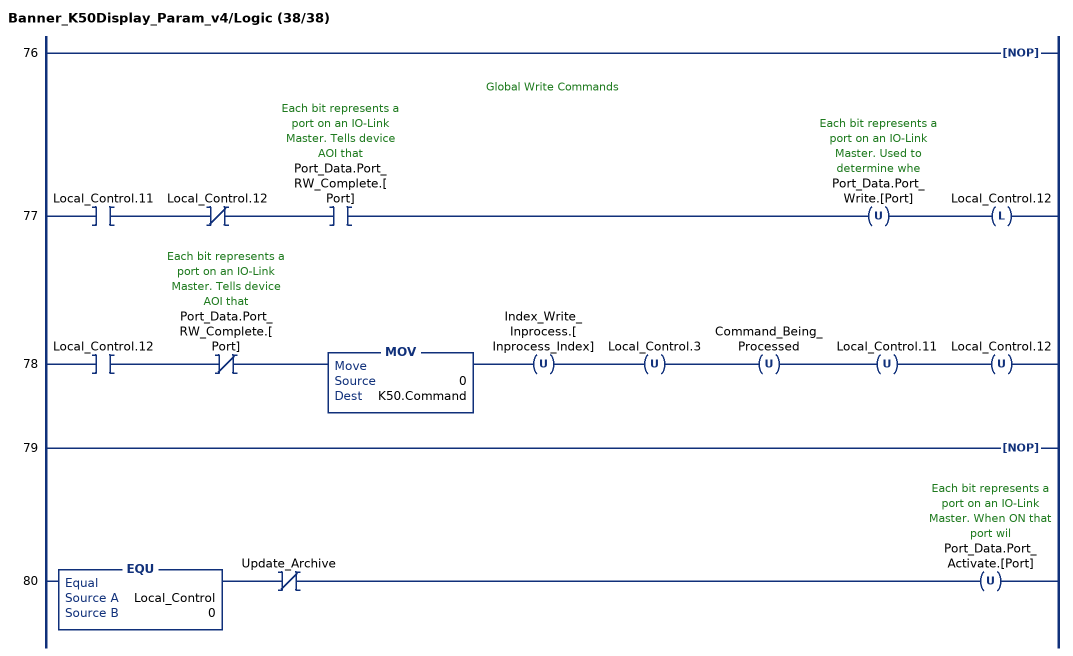
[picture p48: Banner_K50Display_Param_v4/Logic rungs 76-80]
   76: NOP();
   // Global Write Commands
   77: XIC(Local_Control.11)XIO(Local_Control.12)XIC(Port_Data.Port_RW_Complete.[Port])OTU(Port_Data.Port_Write.[Port])OTL(Local_Control.12);
   78: XIC(Local_Control.12)XIO(Port_Data.Port_RW_Complete.[Port])MOV(0,K50.Command)OTU(Index_Write_Inprocess.[Inprocess_Index])OTU(Local_Control.3)OTU(Command_Being_Processed)OTU(Local_Control.11)OTU(Local_Control.12);
   79: NOP();
   80: EQU(Local_Control,0)XIO(Update_Archive)OTU(Port_Data.Port_Activate.[Port]);
END_ROUTINE
END_ADD_ON_INSTRUCTION
